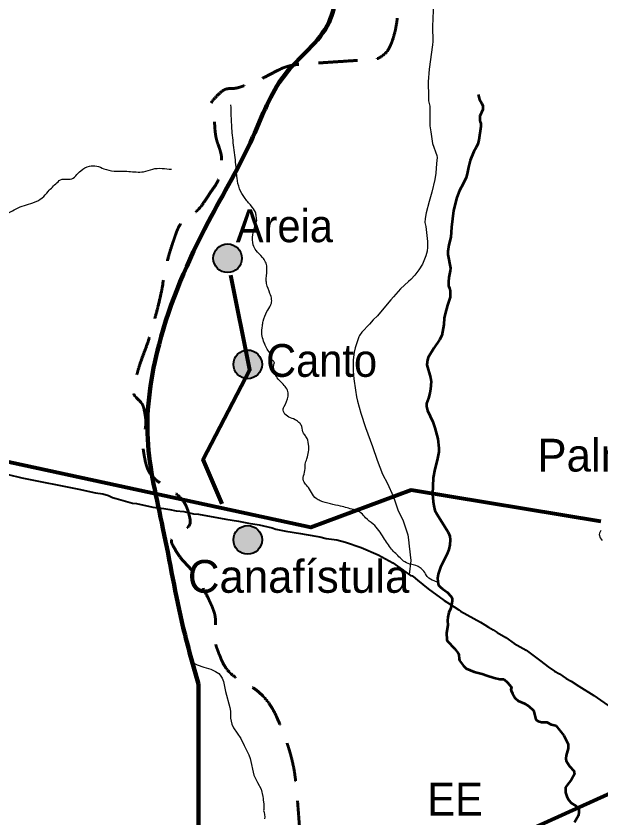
# Model space of a CAD drawing. Extents: x 553962 to 842807, y 8883888 to 9032388.
# Drawn here: x 747736 to 756667, y 8955756 to 8967998 of the extents above; entities that cross this region are included whole.
import ezdxf

# ---------------------------------------------------------------- set-up
doc = ezdxf.new("R2010")
doc.units = 0
doc.header["$LTSCALE"] = 200
doc.linetypes.add('MEDIUM_DASHED', pattern=[4.5, 3, -1.5])
for name, color, linetype, lineweight in [('10', 7, 'MEDIUM_DASHED', 60), ('12', 7, 'Continuous', 25), ('21', 7, 'Continuous', 25), ('24', 7, 'Continuous', 25), ('28', 7, 'Continuous', 40), ('41', 7, 'Continuous', 40), ('9', 7, 'Continuous', 90)]:
    doc.layers.add(name, color=color, linetype=linetype, lineweight=lineweight)

msp = doc.modelspace()

# ---------------------------------------------------------------- hatches: boundary and pattern name
at = {"layer": '41'}
for points in [[(751184.6, 8964300, 1), (750747, 8964300, 1)], [(751492.9, 8962680.6, 1), (751055.3, 8962680.6, 1)], [(751492.9, 8960000.9, 1), (751055.3, 8960000.9, 1)]]:
    msp.add_hatch(color=256, dxfattribs=at).paths.add_polyline_path(points)

# ---------------------------------------------------------------- linework, layer by layer
at = {"layer": '10'}
msp.add_spline([(753353.8, 8967411.3), (753402.1, 8967459.7), (753447.5, 8967537.9), (753569.9, 8968137.4), (753569.9, 8968618.2), (753685.3, 8969252.9), (753896.8, 8969522.2), (753935.3, 8969791.5), (753646.8, 8970214.6), (753242.9, 8970791.6), (753050.6, 8971291.7), (752896.7, 8971618.7), (753127.5, 8972484.2), (753300.6, 8973080.5), (753550.6, 8973484.4), (753646.8, 8973869.1), (753589.1, 8974215.3), (753589.1, 8974484.5), (753704.5, 8974811.5), (753723.7, 8975177), (753762.2, 8975427), (754089.2, 8975773.2), (754377.7, 8976100.2), (754550.8, 8976561.8), (754531.6, 8976946.5), (754538.8, 8979865.5)], degree=3, dxfattribs=at)
for points in [[(751718.9, 8957290.2), (751531.6, 8957712.2), (750995.8, 8957861.4), (750836, 8958259.9), (750739.1, 8958501.4), (750810.6, 8958803), (750701.7, 8959043.4), (750649.5, 8959158.5), (750585.8, 8959273.1), (750522.6, 8959379.2), (750416.4, 8959557.6), (750245.2, 8959714.4), (750142.1, 8959894), (750059.8, 8960037.4), (750424.3, 8960195.8), (750388.3, 8960341.7), (750306, 8960675.5), (749757.2, 8960933.4), (749694.4, 8961281.9), (749657.1, 8961488.8), (749737.2, 8961760.6), (749694.4, 8961975.8), (749670.2, 8962097.1), (749510.2, 8962210.1), (749537.7, 8962334), (749613.3, 8962675.1), (749758.5, 8963019.6), (749851.1, 8963363.7), (749964, 8963783.7), (750022.5, 8964223.4), (750164.5, 8964639.7), (750243.4, 8964871.2), (750497.6, 8964991.5), (750634.5, 8965199.3), (750728.3, 8965341.6), (750833.7, 8965482.3), (750858.4, 8965647), (750892.9, 8965877.2), (750782, 8966109.4), (750768.8, 8966340.9), (750760.8, 8966481.8), (750668.1, 8966638.3), (750791.2, 8966766.2), (750923.4, 8966903.6), (751072.8, 8966882.1), (751216.6, 8966934), (751537.1, 8967049.7), (751840, 8967247.2), (752179.1, 8967269.8), (752291, 8967277.3), (752403, 8967284.8), (752514.9, 8967292.2), (752738.7, 8967307.2), (752962.6, 8967322.1), (753186.4, 8967337), (753247.3, 8967341.1), (753307.9, 8967370.8), (753353.8, 8967411.3)], [(752064, 8949931.3), (752226.2, 8950099), (752371.1, 8950281.5), (752484, 8950494.8), (752727.4, 8950954.4), (752832, 8951444.1), (752990, 8951926.7), (753136.7, 8952374.9), (753359.2, 8952845.2), (753347.9, 8953290.8), (753342, 8953522.6), (753008.5, 8953646.6), (752804.9, 8953784.5), (752471.5, 8954010.4), (751900.3, 8953804.2), (751669.5, 8954179.5), (751384.3, 8954643.3), (752099.3, 8955128.6), (752064.4, 8955611.4), (752024.1, 8956168.6), (751963.7, 8956738.7), (751718.9, 8957290.2)]]:
    msp.add_open_spline(points, degree=3, dxfattribs=at)
at = {"layer": '12'}
for points in [[(753798.1, 8969540.9), (753859.8, 8969409.4), (753909.1, 8969336.8), (753959.2, 8969249.6), (754012.5, 8969179), (754046.6, 8969117.8), (754069.8, 8969065.7), (754101.8, 8968966.1), (754161.6, 8968706.3), (754168.3, 8968520.8), (754116.9, 8968213), (754102.8, 8968082.3), (754094.2, 8967837.6), (754098.2, 8967608.9), (754095, 8967556.7), (754045.7, 8967185.6), (754028.2, 8966994.8), (754035.8, 8966766.1), (754034.7, 8966701.8), (754052, 8966621.5), (754053.6, 8966322.7), (754067.7, 8966231)], [(754067.7, 8966231), (754094.8, 8966053.9), (754159.8, 8965869.2), (754165.3, 8965840.1), (754154.7, 8965744.4), (754145.1, 8965598.1), (754131.9, 8965503.6), (754085.8, 8965310.9), (754041.9, 8965165.6), (753997.3, 8964994.1), (753981.7, 8964906.7), (753979, 8964845.2), (753990.8, 8964783.9), (754019.2, 8964554.2), (754021, 8964470.6), (754014.4, 8964409), (753992.6, 8964335.4), (753941.7, 8964212.4), (753888.1, 8964125.6), (753824, 8964043.5), (753762.8, 8963975.2), (753726.5, 8963946.3), (753606.8, 8963834.6), (753501, 8963710.1), (753459.3, 8963663.9)], [(753459.3, 8963663.9), (753375.2, 8963570.6), (753254.1, 8963422.1), (753189.6, 8963361.6), (753131.1, 8963293.6), (753017.7, 8963172.8), (752982.1, 8963123.5), (752970.7, 8963101.1), (752914.6, 8962932.2), (752900.9, 8962868.1), (752884.4, 8962747.8), (752884.2, 8962579.2), (752893.6, 8962459.8), (752918.2, 8962289)], [(752918.2, 8962289), (752933.3, 8962184.9), (752947.7, 8962120.1), (752999.2, 8961934.7), (753071.9, 8961715.6), (753180.7, 8961424), (753248.1, 8961217.1), (753248.1, 8961217.1), (753333.6, 8961006.6), (753405.8, 8960861.1), (753494.8, 8960666.1), (753525.5, 8960579.3)], [(753525.5, 8960579.3), (753567.3, 8960461.2), (753647.9, 8960293.1), (753719.6, 8960078), (753729.9, 8960000.8), (753736.5, 8959906), (753766.3, 8959686.5), (753736.3, 8959470.4)]]:
    msp.add_lwpolyline(points, dxfattribs=at)
at = {"layer": '12', "lineweight": 40}
for points in [[(746835.1, 8961107.2), (747212.1, 8961045.9), (747363, 8961029.3), (747506.6, 8961018.9), (747617.2, 8960998.5), (747824.8, 8960950.1)], [(747824.8, 8960950.1), (748696.8, 8960775.7), (748951, 8960720.9), (749061.5, 8960701.6), (749146.4, 8960677), (749208.9, 8960650.1), (749264.1, 8960631.6), (749514.7, 8960562.8), (749573.6, 8960554.1), (749824.1, 8960500.3), (749993.7, 8960480.2), (750082, 8960465.4), (750181.5, 8960442.6), (750295.8, 8960435.7), (750443.2, 8960399.6), (750522, 8960394.7), (750939.1, 8960317.4), (751130.9, 8960287.1), (751285.6, 8960255.2), (751447.8, 8960232), (751646.7, 8960184), (751702.1, 8960166.7), (751856.8, 8960132.2), (752079.6, 8960098.7), (752168.1, 8960083)], [(752168.1, 8960083), (752376.2, 8960046), (752473.7, 8960024.1), (752636.8, 8960000.4), (752768, 8959966), (753007.9, 8959884.9), (753265, 8959774.4), (753487.3, 8959648.4), (753758.2, 8959455.5), (753784.2, 8959450.7), (753798.9, 8959443.4), (753866.8, 8959388.1)], [(753866.8, 8959388.1), (754029.7, 8959255.4), (754273.1, 8959074.6), (754315.3, 8959050.4), (754424.8, 8958977.4), (754499, 8958935.4), (754521.9, 8958913.6), (754830.4, 8958745.4), (754896.1, 8958704.8), (754948.1, 8958666.3), (755022.1, 8958627.1), (755080.2, 8958588.1), (755212.9, 8958510.5), (755342.6, 8958419.2), (755526.8, 8958316.3), (755751.2, 8958147.5)], [(755751.2, 8958147.5), (755862.2, 8958064), (755958, 8957996.2), (756032.6, 8957954.2), (756137.7, 8957884), (756214, 8957842.6), (756328.1, 8957767.5), (756559.2, 8957627.5), (756879.8, 8957401.3), (757104, 8957264.6), (757287.1, 8957167.7), (757840.4, 8956875)]]:
    msp.add_lwpolyline(points, dxfattribs=at)
at = {"layer": '21'}
msp.add_lwpolyline([(756667.8, 8960142.8), (756646.1, 8960103.2), (756641.9, 8960082.9), (756655.4, 8960034.6), (756685.1, 8959993.4)], dxfattribs=at)
at = {"layer": '24', "lineweight": 53}
for points in [[(754791, 8966800.1), (754815.2, 8966726), (754850.2, 8966663.9), (754863.5, 8966627.2), (754863, 8966568.8), (754819.6, 8966468.8), (754819.5, 8966405.5), (754823.4, 8966383.8), (754834.5, 8966356.5), (754835.4, 8966312.8), (754803.5, 8966105), (754789.3, 8966046.3), (754763, 8965990.7), (754725.1, 8965929.4), (754670.4, 8965790.2), (754645.4, 8965692), (754625.8, 8965590.1), (754606.6, 8965531.7), (754565, 8965436.8), (754508.3, 8965334.6), (754468.2, 8965229.1), (754418, 8965028.8), (754385.8, 8964773.7), (754376.5, 8964620.7), (754346.6, 8964503.9), (754329.8, 8964405.4), (754330.8, 8964358.1), (754367.8, 8964150.3), (754367.2, 8964106.8), (754343, 8964004.7), (754338.2, 8963942.6), (754341.4, 8963879.5), (754356.8, 8963844.3), (754367.2, 8963800.6), (754364.2, 8963706.1), (754324.4, 8963585.7), (754286.8, 8963450), (754285.7, 8963432), (754273.9, 8963387.1), (754266, 8963290.7), (754236.9, 8963123.5), (754201.7, 8963057.3), (754114.6, 8962926), (754027.8, 8962785.2), (754016.9, 8962748.7), (754010.6, 8962674.3), (754066.2, 8962478), (754076.2, 8962418.6), (754066.8, 8962303.7), (754054.9, 8962239.9), (754034.7, 8962164.2), (754002.5, 8962083.6), (754003.6, 8962036.3), (754018, 8961976.9), (754099.6, 8961801.3), (754131.9, 8961713.6), (754174.2, 8961542.5), (754191.4, 8961398.6), (754193.2, 8961347.2), (754168.7, 8961215.5), (754129.2, 8961079.8), (754106, 8960948.1), (754094.1, 8960701.2), (754103.1, 8960586), (754113, 8960522.2)], [(754113, 8960522.2), (754133.2, 8960450.2), (754164.6, 8960385.9), (754285.4, 8960201), (754333.3, 8960119.1), (754358.5, 8960059.1), (754366.7, 8960003.6), (754361.1, 8959927.4), (754342.9, 8959851.5), (754312.2, 8959776.4), (754218.7, 8959583.9), (754182.3, 8959476.4), (754169.4, 8959412.5), (754180.9, 8959330), (754188.6, 8959309.7), (754216.4, 8959278.5), (754249.1, 8959251.2), (754317.6, 8959205.1), (754378.4, 8959135.3), (754396.6, 8959107.3), (754395.3, 8959068.2), (754385.8, 8959005.2), (754369.7, 8958949.7), (754345.2, 8958889.9), (754331, 8958822.6), (754326, 8958771), (754328.4, 8958699.2), (754310.7, 8958580.2), (754315.6, 8958473.5), (754326.5, 8958456.4), (754433.4, 8958343.3), (754486.5, 8958269.1), (754495.6, 8958248.3), (754500.9, 8958184.1), (754506.9, 8958158.4), (754569.5, 8958079.4), (754610.9, 8958038.6)], [(754610.9, 8958038.6), (754610.9, 8958038.6), (754731.2, 8957987.7), (754791.1, 8957970), (754854.6, 8957958.1), (754922.6, 8957930.3), (755038.2, 8957895.5), (755123.8, 8957875.9), (755185.9, 8957875.1)], [(755185.9, 8957875.1), (755238.8, 8957821.3), (755295.4, 8957755.3), (755298.8, 8957744.7), (755293, 8957714.3), (755295, 8957700.2), (755316.4, 8957655.1), (755359, 8957583.6), (755405.6, 8957545), (755497.6, 8957501.2), (755563.5, 8957459.9), (755635.5, 8957398.1), (755644, 8957381.6), (755650.3, 8957338.2), (755674.1, 8957259.6), (755682.8, 8957247.8), (755709.3, 8957231.1), (755761.1, 8957215.6), (755838.8, 8957216.3), (755909.4, 8957183.9), (755979.1, 8957165.2)], [(755979.1, 8957165.2), (756099.8, 8957011.9), (756133.3, 8956953.6), (756164.7, 8956883.8)], [(756164.7, 8956883.8), (756167.7, 8956814.9), (756135.2, 8956708.9), (756132.8, 8956661.9), (756136.2, 8956626.4), (756187.9, 8956545.8), (756252.7, 8956472.7), (756258.8, 8956454.4), (756261.3, 8956424.2), (756215.1, 8956340.9), (756146.2, 8956251.2), (756128.1, 8956221.2), (756124, 8956199.7), (756128.2, 8956143.1), (756146.9, 8956084.8), (756173.9, 8956031), (756217.2, 8955981.5), (756283.3, 8955940.1), (756321.8, 8955893.7), (756329.4, 8955877.8), (756331.8, 8955847), (756324.5, 8955795.2), (756263.6, 8955684.9)]]:
    msp.add_lwpolyline(points, dxfattribs=at)
at = {"layer": '24'}
for points in [[(754791, 8966800.1), (754815.2, 8966726), (754850.2, 8966663.9), (754863.5, 8966627.2), (754863, 8966568.8), (754819.6, 8966468.8), (754819.5, 8966405.5), (754823.4, 8966383.8), (754834.5, 8966356.5), (754835.4, 8966312.8), (754803.5, 8966105), (754789.3, 8966046.3), (754763, 8965990.7), (754725.1, 8965929.4), (754670.4, 8965790.2), (754645.4, 8965692), (754625.8, 8965590.1), (754606.6, 8965531.7), (754565, 8965436.8), (754508.3, 8965334.6), (754468.2, 8965229.1), (754418, 8965028.8), (754385.8, 8964773.7), (754376.5, 8964620.7), (754346.6, 8964503.9), (754329.8, 8964405.4), (754330.8, 8964358.1), (754367.8, 8964150.3), (754367.2, 8964106.8), (754343, 8964004.7), (754338.2, 8963942.6), (754341.4, 8963879.5), (754356.8, 8963844.3), (754367.2, 8963800.6), (754364.2, 8963706.1), (754324.4, 8963585.7), (754286.8, 8963450), (754285.7, 8963432), (754273.9, 8963387.1), (754266, 8963290.7), (754236.9, 8963123.5), (754201.7, 8963057.3), (754114.6, 8962926), (754027.8, 8962785.2), (754016.9, 8962748.7), (754010.6, 8962674.3), (754066.2, 8962478), (754076.2, 8962418.6), (754066.8, 8962303.7), (754054.9, 8962239.9), (754034.7, 8962164.2), (754002.5, 8962083.6), (754003.6, 8962036.3), (754018, 8961976.9), (754099.6, 8961801.3), (754131.9, 8961713.6), (754174.2, 8961542.5), (754191.4, 8961398.6), (754193.2, 8961347.2), (754168.7, 8961215.5), (754129.2, 8961079.8), (754106, 8960948.1), (754094.1, 8960701.2), (754103.1, 8960586), (754113, 8960522.2)], [(754113, 8960522.2), (754133.2, 8960450.2), (754164.6, 8960385.9), (754285.4, 8960201), (754333.3, 8960119.1), (754358.5, 8960059.1), (754366.7, 8960003.6), (754361.1, 8959927.4), (754342.9, 8959851.5), (754312.2, 8959776.4), (754218.7, 8959583.9), (754182.3, 8959476.4), (754169.4, 8959412.5), (754180.9, 8959330), (754188.6, 8959309.7), (754216.4, 8959278.5), (754249.1, 8959251.2), (754317.6, 8959205.1), (754378.4, 8959135.3), (754396.6, 8959107.3), (754395.3, 8959068.2), (754385.8, 8959005.2), (754369.7, 8958949.7), (754345.2, 8958889.9), (754331, 8958822.6), (754326, 8958771), (754328.4, 8958699.2), (754310.7, 8958580.2), (754315.6, 8958473.5), (754326.5, 8958456.4), (754433.4, 8958343.3), (754486.5, 8958269.1), (754495.6, 8958248.3), (754500.9, 8958184.1), (754506.9, 8958158.4), (754569.5, 8958079.4), (754610.9, 8958038.6)], [(750423.6, 8958135.7), (750499.6, 8958092.9), (750602.7, 8958055.6), (750709.5, 8958026.2), (750782, 8957991.5), (750830.2, 8957961.5), (750855.2, 8957933.6), (750884.2, 8957892.1), (750902.2, 8957841), (750932.8, 8957688.1), (751002.6, 8957440.2), (751011.1, 8957385.5), (751012.3, 8957279.8), (751029.1, 8957185.3), (751054.7, 8957130.6), (751168.1, 8956969), (751218.5, 8956860.1), (751291.5, 8956717.4), (751311.6, 8956662.7), (751365.8, 8956411.3), (751423, 8956298.1), (751477.7, 8956195.2), (751505.7, 8956084.4)], [(754610.9, 8958038.6), (754610.9, 8958038.6), (754731.2, 8957987.7), (754791.1, 8957970), (754854.6, 8957958.1), (754922.6, 8957930.3), (755038.2, 8957895.5), (755123.8, 8957875.9), (755185.9, 8957875.1)], [(755185.9, 8957875.1), (755238.8, 8957821.3), (755295.4, 8957755.3), (755298.8, 8957744.7), (755293, 8957714.3), (755295, 8957700.2), (755316.4, 8957655.1), (755359, 8957583.6), (755405.6, 8957545), (755497.6, 8957501.2), (755563.5, 8957459.9), (755635.5, 8957398.1), (755644, 8957381.6), (755650.3, 8957338.2), (755674.1, 8957259.6), (755682.8, 8957247.8), (755709.3, 8957231.1), (755761.1, 8957215.6), (755838.8, 8957216.3), (755909.4, 8957183.9), (755979.1, 8957165.2)], [(755979.1, 8957165.2), (756099.8, 8957011.9), (756133.3, 8956953.6), (756164.7, 8956883.8)], [(756164.7, 8956883.8), (756167.7, 8956814.9), (756135.2, 8956708.9), (756132.8, 8956661.9), (756136.2, 8956626.4), (756187.9, 8956545.8), (756252.7, 8956472.7), (756258.8, 8956454.4), (756261.3, 8956424.2), (756215.1, 8956340.9), (756146.2, 8956251.2), (756128.1, 8956221.2), (756124, 8956199.7), (756128.2, 8956143.1), (756146.9, 8956084.8), (756173.9, 8956031), (756217.2, 8955981.5), (756283.3, 8955940.1), (756321.8, 8955893.7), (756329.4, 8955877.8), (756331.8, 8955847), (756324.5, 8955795.2), (756263.6, 8955684.9)], [(751505.7, 8956084.4), (751507.4, 8956055.1), (751508.1, 8956042.7), (751510.5, 8956026.3), (751513.5, 8956003.2), (751520.2, 8955965.6), (751521.6, 8955957.9), (751521.9, 8955951.5), (751522.8, 8955950.1)], [(751520.4, 8955950.1), (751521.7, 8955924.3), (751521.1, 8955909.7), (751519.5, 8955892.5), (751517.2, 8955883.6), (751515.1, 8955868.8), (751519.1, 8955855.6), (751523.6, 8955846.3), (751529.6, 8955801.9), (751533.5, 8955770.7), (751531.2, 8955742.9)]]:
    msp.add_lwpolyline(points, dxfattribs=at)
for points in [[(754168.1, 8959356.7), (754118.5, 8959373.3), (754015.9, 8959439.5), (753963, 8959522.3), (753920, 8959565.3), (753863.7, 8959601.7), (753777.7, 8959624.9), (753671.8, 8959664.6), (753599, 8959727.5), (753470, 8959860), (753347.6, 8960035.4), (753188.7, 8960240.7), (753072.9, 8960336.7), (753006.8, 8960409.6), (752887.7, 8960462.5), (752692.4, 8960515.5), (752381.4, 8960598.3), (752318.6, 8960631.4), (752182.9, 8960823.4), (752133.3, 8960879.7), (752149.8, 8961088.3), (752153.1, 8961154.5), (752176.3, 8961240.6), (752202.8, 8961346.5), (752202.8, 8961459.1), (752163.1, 8961578.2), (752126.7, 8961627.9), (752100.2, 8961730.6), (752067.1, 8961783.5), (752020.8, 8961823.2), (751842.1, 8961922.6), (751815.6, 8962002), (751828.9, 8962035.1), (751891.7, 8962194.1), (751891.7, 8962247), (751799.1, 8962392.7), (751723, 8962475.5), (751686.6, 8962551.6), (751673.4, 8962674.1), (751680, 8962710.5), (751646.7, 8962746), (751629.2, 8962814.3), (751582.4, 8962896.2), (751541.5, 8962972.3), (751516.1, 8963036.6), (751490.8, 8963138), (751498.6, 8963270.7), (751510.3, 8963338.9), (751566.8, 8963485.2), (751623.3, 8963580.8), (751638.9, 8963627.6), (751638.9, 8963670.5), (751613.6, 8963762.2), (751561, 8963914.3), (751555.1, 8963990.3), (751566.8, 8964163.9), (751545.4, 8964241.9), (751500.6, 8964314.1), (751401.2, 8964419.4), (751358.3, 8964503.3), (751350.5, 8964659.3), (751381.7, 8964780.2), (751408.9, 8964864.1), (751405, 8964942.1), (751391.4, 8965002.6), (751327.1, 8965100.1), (751223.8, 8965226.9), (751149.7, 8965359.5), (751110.7, 8965523.3), (751102.9, 8965618.9), (751071.8, 8965913.4), (751038.6, 8966215.7), (751023, 8966471), (751017.2, 8966644)], [(748358.1, 8965451.5), (748438.1, 8965506.5), (748563, 8965506.5), (748723, 8965636.5), (748857.9, 8965706.6), (748967.9, 8965706.6), (749077.8, 8965666.6), (749232.8, 8965631.5), (749457.7, 8965626.5), (749682.7, 8965621.5), (749822.6, 8965661.6), (750112, 8965657.9)], [(738367.7, 8959924.4), (738437.2, 8960071.1), (738471.9, 8960121.3), (738537.5, 8960171.6), (738630.2, 8960202.5), (738765.3, 8960248.8), (738950.5, 8960322.2), (739124.2, 8960357), (739313.4, 8960368.5), (739359.7, 8960368.5), (739506.3, 8960291.3), (739610.6, 8960229.5), (739660.8, 8960198.6), (739703.2, 8960210.2), (739761.1, 8960275.8), (739826.7, 8960310.6), (739919.4, 8960314.5), (740031.3, 8960372.4), (740096.9, 8960453.5), (740178, 8960523), (740239.7, 8960542.3), (740340.1, 8960557.8), (740509.9, 8960496), (740648.9, 8960465.1), (740753.1, 8960465.1), (740865, 8960488.3), (740926.8, 8960519.2), (741135.2, 8960677.5), (741193.1, 8960747.1), (741278, 8960812.7), (741293.5, 8960851.3), (741300.5, 8960850.1), (741255.5, 8960925.1), (741195.5, 8961035.2), (741220.5, 8961105.2), (741225.5, 8961275.2), (741235.5, 8961375.3), (741255.5, 8961460.3), (741305.5, 8961510.3), (741355.4, 8961545.3), (741395.4, 8961605.3), (741440.4, 8961675.3), (741500.4, 8961730.4), (741545.4, 8961795.4), (741540.4, 8961925.4), (741555.4, 8962015.5), (741660.3, 8962135.5), (741690.3, 8962305.5), (741680.3, 8962425.6), (741700.3, 8962620.6), (741780.3, 8962700.7), (741975.2, 8962690.7), (742105.2, 8962630.6), (742195.2, 8962590.6), (742275.1, 8962580.6), (742390.1, 8962640.6), (742520.1, 8962655.6), (742770, 8962605.6), (742989.9, 8962550.6), (743104.8, 8962540.6), (743324.8, 8962590.6), (743524.7, 8962640.6), (743664.7, 8962635.6), (743774.6, 8962635.6), (743904.6, 8962675.7), (744079.5, 8962775.7), (744274.5, 8962990.7), (744539.4, 8963385.9), (744659.3, 8963580.9), (744879.3, 8963706), (745084.2, 8963786), (745299.1, 8963801), (745444.1, 8963831), (745664, 8963901), (745943.9, 8964026.1), (746173.8, 8964201.1), (746393.8, 8964276.1), (746543.7, 8964266.1), (746708.6, 8964376.2), (746898.6, 8964536.2), (747118.5, 8964656.2), (747248.5, 8964676.2), (747398.4, 8964766.3), (747428.4, 8964831.3), (747488.4, 8964891.3), (747623.3, 8964991.3), (747863.3, 8965106.4), (747993.2, 8965146.4), (748133.2, 8965221.4), (748228.1, 8965321.5), (748358.1, 8965451.5)]]:
    msp.add_spline(points, degree=3, dxfattribs=at)
at = {"layer": '28', "lineweight": 80}
msp.add_line((757134.6, 8956280.5), (754888.4, 8955266.6), dxfattribs=at)
for points in [[(756666.9, 8960280.5), (753769.9, 8960761.1), (752238.8, 8960190.3), (744706.3, 8961816), (738249.1, 8961416.3), (734964.7, 8968490.1), (734839.6, 8970305.5)], [(750882.5, 8960553.4), (750593.5, 8961228.1), (751306.4, 8962596.9), (751017.4, 8964042.8)]]:
    msp.add_lwpolyline(points, dxfattribs=at)
at = {"layer": '41'}
for centre in [(750965.8, 8964300), (751274.1, 8962680.6), (751274.1, 8960000.9)]:
    msp.add_circle(centre, 218.8, dxfattribs=at)
at = {"layer": '9'}
msp.add_lwpolyline([(737921.5, 8948812.5), (740981.3, 8950253.8), (750519.5, 8951321.2), (750521.5, 8957798.6)], dxfattribs=at)
msp.add_spline([(750521.5, 8957798.6), (750290, 8958657.6), (749980, 8960173.9), (749746.6, 8961538.9), (749919.1, 8962982.1), (750673.6, 8964858.9), (751354.2, 8966153.2), (751832.9, 8967092.2), (752515.2, 8967905.8), (752689.9, 8968716.5), (752991.6, 8969502.6), (753167.8, 8969908.5), (753010.5, 8971299.2), (753439.5, 8973954.2)], degree=3, dxfattribs=at)

# ---------------------------------------------------------------- texts
at = {"layer": '41', "width": 0.95}
for s, p in [('Areia', (751091.9, 8964545.4)), ('Canto', (751554.1, 8962490.1)), ('EE', (754016.4, 8955792.7))]:
    msp.add_text(s, height=500, dxfattribs=at).set_placement(p)
at = {"layer": '41'}
for s, p in [('Palmeira dos Índios', (755696.3, 8961044.2)), ('Canafístula', (750359.6, 8959193.5))]:
    msp.add_text(s, height=500, dxfattribs=at).set_placement(p)

doc.saveas('drawing.dxf')
